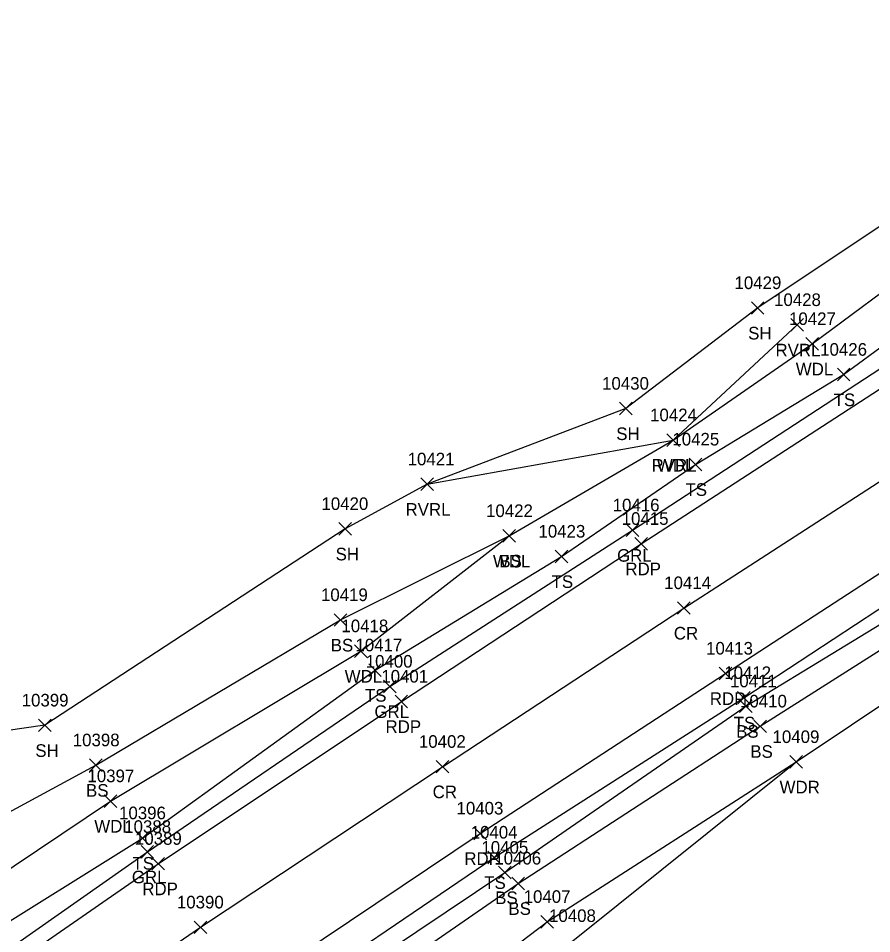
# Model space of a CAD drawing. Extents: x 1651685 to 1653558, y 889533 to 891085.
# Drawn here: x 1652971.5 to 1653107, y 890725 to 890870.3 of the extents above; entities that cross this region are included whole.
import ezdxf

# ---------------------------------------------------------------- set-up
doc = ezdxf.new("R2010")
doc.units = 0
for name, color, linetype in [('L_A', 7, 'Continuous'), ('L_I', 7, 'Continuous'), ('L_TIC', 7, 'Continuous'), ('LAWA', 7, 'Continuous'), ('LAWE', 7, 'Continuous'), ('LELB', 7, 'Continuous'), ('LSOGP', 7, 'Continuous'), ('P_A', 7, 'Continuous'), ('P_I', 7, 'Continuous'), ('P_TIC', 7, 'Continuous'), ('PET', 7, 'Continuous'), ('PRC', 7, 'Continuous'), ('R_A', 7, 'Continuous'), ('R_I', 7, 'Continuous'), ('R_TIC', 7, 'Continuous'), ('RGR', 7, 'Continuous')]:
    doc.layers.add(name, color=color, linetype=linetype)

msp = doc.modelspace()

# ---------------------------------------------------------------- linework, layer by layer
at = {"layer": 'L_TIC'}
for points in [[(1653087.88, 890823.36), (1653089.88, 890825.36)], [(1653089.88, 890823.36), (1653087.88, 890825.36)], [(1653094.15, 890820.67), (1653096.15, 890822.67)], [(1653096.15, 890820.67), (1653094.15, 890822.67)], [(1653096.52, 890817.66), (1653098.52, 890819.66)], [(1653098.52, 890817.66), (1653096.52, 890819.66)], [(1653101.53, 890812.78), (1653103.53, 890814.78)], [(1653103.53, 890812.78), (1653101.53, 890814.78)], [(1653066.94, 890807.39), (1653068.94, 890809.39)], [(1653068.94, 890807.39), (1653066.94, 890809.39)], [(1653074.47, 890802.38), (1653076.47, 890804.38)], [(1653076.47, 890802.38), (1653074.47, 890804.38)], [(1653074.47, 890802.38), (1653076.47, 890804.38)], [(1653076.47, 890802.38), (1653074.47, 890804.38)], [(1653078.01, 890798.53), (1653080.01, 890800.53)], [(1653080.01, 890798.53), (1653078.01, 890800.53)], [(1653035.42, 890795.38), (1653037.42, 890797.38)], [(1653037.42, 890795.38), (1653035.42, 890797.38)], [(1653022.39, 890788.29), (1653024.39, 890790.29)], [(1653024.39, 890788.29), (1653022.39, 890790.29)], [(1653048.43, 890787.17), (1653050.43, 890789.17)], [(1653050.43, 890787.17), (1653048.43, 890789.17)], [(1653048.43, 890787.17), (1653050.43, 890789.17)], [(1653050.43, 890787.17), (1653048.43, 890789.17)], [(1653056.75, 890783.91), (1653058.75, 890785.91)], [(1653058.75, 890783.91), (1653056.75, 890785.91)], [(1653021.66, 890773.83), (1653023.66, 890775.83)], [(1653023.66, 890773.83), (1653021.66, 890775.83)], [(1653024.9, 890768.89), (1653026.9, 890770.89)], [(1653026.9, 890768.89), (1653024.9, 890770.89)], [(1653027.13, 890765.86), (1653029.13, 890767.86)], [(1653029.13, 890765.86), (1653027.13, 890767.86)], [(1653085.67, 890761.46), (1653087.67, 890763.46)], [(1653087.67, 890761.46), (1653085.67, 890763.46)], [(1653086.02, 890760.14), (1653088.02, 890762.14)], [(1653088.02, 890760.14), (1653086.02, 890762.14)], [(1652974.72, 890757.1), (1652976.72, 890759.1)], [(1652976.72, 890757.1), (1652974.72, 890759.1)], [(1653088.27, 890756.95), (1653090.27, 890758.95)], [(1653090.27, 890756.95), (1653088.27, 890758.95)], [(1653094, 890751.3), (1653096, 890753.3)], [(1653096, 890751.3), (1653094, 890753.3)], [(1652982.82, 890750.78), (1652984.82, 890752.78)], [(1652984.82, 890750.78), (1652982.82, 890752.78)], [(1652985.15, 890745.08), (1652987.15, 890747.08)], [(1652987.15, 890745.08), (1652985.15, 890747.08)], [(1652990.22, 890739.2), (1652992.22, 890741.2)], [(1652992.22, 890739.2), (1652990.22, 890741.2)], [(1653046.06, 890736.13), (1653048.06, 890738.13)], [(1653048.06, 890736.13), (1653046.06, 890738.13)], [(1653047.76, 890733.73), (1653049.76, 890735.73)], [(1653049.76, 890733.73), (1653047.76, 890735.73)], [(1653049.87, 890732.01), (1653051.87, 890734.01)], [(1653051.87, 890732.01), (1653049.87, 890734.01)], [(1653054.48, 890725.92), (1653056.48, 890727.92)], [(1653056.48, 890725.92), (1653054.48, 890727.92)]]:
    msp.add_lwpolyline(points, dxfattribs=at)
at = {"layer": 'LAWA'}
for points in [[(1652817.98, 890613.54), (1652840.14, 890627.46), (1652861.15, 890647.29), (1652878.51, 890666.18), (1652884.26, 890671.52), (1652922.69, 890701.4), (1652959.19, 890728.02), (1652986.15, 890746.08), (1653025.9, 890769.89), (1653049.43, 890788.17), (1653075.47, 890803.38), (1653097.52, 890818.66), (1653132.33, 890844.48)], [(1652833.35, 890477.68), (1652833.39, 890492.3), (1652850.18, 890532.6), (1652867.73, 890564.2), (1652876.6, 890576.01), (1652892.95, 890598.85), (1652902.11, 890607.6), (1652908.8, 890618.44), (1652924.22, 890630.58), (1652962.12, 890654.07), (1652988.27, 890674.02), (1653019.66, 890699.72), (1653055.48, 890726.92), (1653095, 890752.3), (1653138.9, 890781.66), (1653162.63, 890798.14), (1653173.84, 890802.86)]]:
    msp.add_lwpolyline(points, dxfattribs=at)
at = {"layer": 'LAWE'}
msp.add_lwpolyline([(1653036.42, 890796.38), (1653075.47, 890803.38), (1653095.15, 890821.67)], dxfattribs=at)
at = {"layer": 'LELB'}
for points in [[(1652773.03, 890464.56), (1652787.9, 890509.35), (1652802.92, 890548.75), (1652814.17, 890571.87), (1652832.16, 890602.17), (1652848.73, 890624.66), (1652866.01, 890644.23), (1652889.12, 890668.57), (1652926.33, 890696.32), (1652964.24, 890723.35), (1652991.22, 890740.2), (1653028.13, 890766.86), (1653057.75, 890784.91), (1653079.01, 890799.53), (1653102.53, 890813.78), (1653139.28, 890840.79)], [(1652801.17, 890441.9), (1652819.95, 890497.78), (1652834.5, 890541.46), (1652846.59, 890562.12), (1652860.39, 890582.03), (1652876.07, 890602.68), (1652893.78, 890623.65), (1652912.56, 890642.08), (1652928.52, 890655.01), (1652947.04, 890668.65), (1652977.97, 890691.06), (1653009.95, 890711.96), (1653047.06, 890737.13), (1653086.67, 890762.46), (1653129.22, 890790.4), (1653161.56, 890810.77), (1653178.09, 890819.36), (1653180.64, 890814.31), (1653173.84, 890802.86)], [(1652803.19, 890441), (1652820.95, 890497.33), (1652835.58, 890541.15), (1652847.79, 890560.97), (1652861.63, 890580.86), (1652877.83, 890601.57), (1652890.21, 890617.22), (1652895.56, 890622.27), (1652897.12, 890622.95), (1652897.22, 890624.03), (1652915.57, 890639.3), (1652930.05, 890653.23), (1652948.11, 890667.03), (1652978.83, 890689.41), (1653011.67, 890709.88), (1653048.76, 890734.73), (1653087.02, 890761.14), (1653131.31, 890788.11), (1653159.98, 890805.73), (1653164.16, 890807.03), (1653164.17, 890807.66), (1653169.82, 890813.7), (1653178.09, 890819.36)], [(1652803.19, 890441), (1652822.35, 890480.19), (1652822.96, 890495.87), (1652838.19, 890539.83), (1652849.62, 890560.27), (1652863.19, 890579.04), (1652878.87, 890600.11), (1652891.82, 890615.8), (1652896.5, 890621.01), (1652897.47, 890622.7), (1652898.8, 890623.23), (1652915.57, 890639.3), (1652950.1, 890665.22), (1652980.52, 890686.66), (1653013.67, 890707.26), (1653050.87, 890733.01), (1653089.27, 890757.95), (1653133.42, 890785.98), (1653160.95, 890802.08), (1653164.63, 890804.85), (1653167.22, 890806.35), (1653170.81, 890811.17), (1653178.09, 890819.36)], [(1652740.63, 890407.57), (1652746.83, 890413.23), (1652755.32, 890445.88), (1652760.35, 890468.2), (1652780.77, 890512.23), (1652796.45, 890551.5), (1652807.59, 890577.74), (1652825.47, 890605.79), (1652840.14, 890627.46), (1652854.42, 890651.04), (1652870.71, 890668.15), (1652876.32, 890668.87), (1652880.71, 890674.05), (1652916.29, 890707.34), (1652954.78, 890736.09), (1652983.82, 890751.78), (1653022.66, 890774.83), (1653049.43, 890788.17)]]:
    msp.add_lwpolyline(points, dxfattribs=at)
at = {"layer": 'LSOGP'}
for points in [[(1653191.35, 890868.11), (1653139.25, 890847.21), (1653133.81, 890854.84), (1653132.26, 890853.62), (1653128.23, 890850.65), (1653088.88, 890824.36), (1653067.93, 890808.39), (1653036.42, 890796.38), (1653023.39, 890789.29), (1652975.72, 890758.11), (1652938.51, 890752.73), (1652900.6, 890736.09), (1652902.13, 890723.86), (1652868.79, 890705.34), (1652839.11, 890687.76), (1652822.21, 890657.08), (1652787.43, 890617.81), (1652783.5, 890592.65), (1652777.63, 890568.95), (1652768.73, 890549.07), (1652760.18, 890544.48), (1652755.23, 890514.52), (1652738.16, 890487.37)], [(1652860.84, 890470.43), (1652866.91, 890496.63), (1652876.03, 890531.03), (1652888.38, 890556.27), (1652912.99, 890585.04), (1652934.21, 890597.75), (1652965.72, 890622.73), (1652993.55, 890638.61), (1652995.94, 890655.58), (1652988.27, 890674.02), (1653019.66, 890699.72), (1653059.51, 890723.89), (1653095, 890752.3), (1653138.9, 890781.66), (1653162.63, 890798.14), (1653173.85, 890802.86), (1653182.19, 890805.28), (1653198.8, 890815.08)]]:
    msp.add_lwpolyline(points, dxfattribs=at)
at = {"layer": 'P_TIC'}
for points in [[(1653069.4, 890785.93), (1653071.4, 890787.93)], [(1653071.4, 890785.93), (1653069.4, 890787.93)], [(1653076.14, 890775.73), (1653078.14, 890777.73)], [(1653078.14, 890775.73), (1653076.14, 890777.73)], [(1653082.79, 890765.34), (1653084.79, 890767.34)], [(1653084.79, 890765.34), (1653082.79, 890767.34)], [(1653031.31, 890760.89), (1653033.31, 890762.89)], [(1653033.31, 890760.89), (1653031.31, 890762.89)], [(1653037.85, 890750.54), (1653039.85, 890752.54)], [(1653039.85, 890750.54), (1653037.85, 890752.54)], [(1653043.82, 890739.95), (1653045.82, 890741.95)], [(1653045.82, 890739.95), (1653043.82, 890741.95)], [(1652992.7, 890735.14), (1652994.7, 890737.14)], [(1652994.7, 890735.14), (1652992.7, 890737.14)], [(1652999.43, 890725.04), (1653001.43, 890727.04)], [(1653001.43, 890725.04), (1652999.43, 890727.04)]]:
    msp.add_lwpolyline(points, dxfattribs=at)
at = {"layer": 'PET'}
for points in [[(1652776.68, 890458.63), (1652791.9, 890507.53), (1652801.72, 890533.82), (1652810.09, 890553.36), (1652823.07, 890577.38), (1652836.65, 890598.71), (1652853.5, 890620.62), (1652874.5, 890644.55), (1652894.69, 890663.43), (1652909.83, 890677.02), (1652929.28, 890691.96), (1652967.44, 890717.98), (1652993.7, 890736.14), (1653032.31, 890761.89), (1653070.4, 890786.93), (1653112.15, 890813.99), (1653148.48, 890837.47), (1653192.87, 890865.71), (1653235.94, 890893.09), (1653280.18, 890921.16), (1653320.29, 890946.68)], [(1652797.7, 890444.76), (1652815.98, 890499.36), (1652826.44, 890526.94), (1652833.17, 890541.97), (1652844.38, 890563.93), (1652857.27, 890583.87), (1652872.84, 890604.95), (1652891.59, 890626.08), (1652910.84, 890643.86), (1652926.01, 890657.3), (1652944.49, 890672.05), (1652975.79, 890694.46), (1653007.52, 890715.91), (1653044.82, 890740.95), (1653083.79, 890766.34), (1653126.92, 890794.39), (1653162.42, 890817.19), (1653177.23, 890826.53), (1653212.82, 890849.27), (1653251.6, 890873.99), (1653294.22, 890900.69), (1653334.65, 890925.85)]]:
    msp.add_lwpolyline(points, dxfattribs=at)
at = {"layer": 'PRC'}
msp.add_lwpolyline([(1652786.21, 890448.94), (1652804.54, 890503.78), (1652815.08, 890532.72), (1652822.08, 890547.99), (1652834.04, 890571.05), (1652846.73, 890591.11), (1652862.72, 890612.73), (1652882.99, 890635.62), (1652902.76, 890654.37), (1652917.73, 890667.19), (1652936.47, 890681.71), (1652967.99, 890703.84), (1653000.43, 890726.04), (1653038.85, 890751.54), (1653077.14, 890776.73), (1653119.4, 890804.03), (1653156.21, 890827.39), (1653198.86, 890855.33), (1653243.54, 890883.44), (1653287.35, 890911.24), (1653327.74, 890936.2)], dxfattribs=at)
at = {"layer": 'R_TIC'}
for points in [[(1653068.01, 890788.08), (1653070.01, 890790.08)], [(1653070.01, 890788.08), (1653068.01, 890790.08)], [(1653029.5, 890763.27), (1653031.5, 890765.27)], [(1653031.5, 890763.27), (1653029.5, 890765.27)], [(1652990.99, 890737.03), (1652992.99, 890739.03)], [(1652992.99, 890737.03), (1652990.99, 890739.03)]]:
    msp.add_lwpolyline(points, dxfattribs=at)
at = {"layer": 'RGR'}
msp.add_lwpolyline([(1652753.62, 890407.5), (1652763.75, 890431.04), (1652774.48, 890459.79), (1652790.93, 890508.17), (1652800.51, 890534.29), (1652809.1, 890554.07), (1652821.88, 890578.18), (1652835.53, 890599.08), (1652852.44, 890621.25), (1652873.86, 890645.38), (1652894.3, 890664.88), (1652909.53, 890677.55), (1652928.71, 890692.69), (1652967.13, 890720.62), (1652991.99, 890738.03), (1653030.5, 890764.27), (1653069.01, 890789.08), (1653110.73, 890816.31), (1653147.12, 890839.54), (1653191.34, 890868.1), (1653234.07, 890895.44), (1653279.07, 890923.79), (1653318.83, 890948.74)], dxfattribs=at)

# ---------------------------------------------------------------- texts
at = {"layer": 'L_A'}
for s, p in [('SH', (1653087.37, 890819.36)), ('RVRL', (1653091.71, 890816.67)), ('WDL', (1653094.93, 890813.66)), ('TS', (1653100.94, 890808.78)), ('SH', (1653066.43, 890803.39)), ('RVRL', (1653072.04, 890798.38)), ('WDL', (1653072.89, 890798.38)), ('TS', (1653077.42, 890794.53)), ('RVRL', (1653032.98, 890791.38)), ('SH', (1653021.88, 890784.29)), ('WDL', (1653046.85, 890783.17)), ('BS', (1653047.87, 890783.17)), ('TS', (1653056.16, 890779.91)), ('BS', (1653021.1, 890769.83)), ('WDL', (1653023.32, 890764.89)), ('TS', (1653026.54, 890761.86)), ('TS', (1653085.08, 890757.46)), ('BS', (1653085.46, 890756.14)), ('SH', (1652974.21, 890753.1)), ('BS', (1653087.71, 890752.95)), ('BS', (1652982.26, 890746.78)), ('WDR', (1653092.36, 890747.3)), ('WDL', (1652983.57, 890741.08)), ('TS', (1652989.63, 890735.2)), ('TS', (1653045.47, 890732.13)), ('BS', (1653047.21, 890729.73)), ('BS', (1653049.31, 890728.01))]:
    msp.add_text(s, height=2, dxfattribs=at).set_placement(p)
at = {"layer": 'L_I'}
for s, p in [('10429', (1653085.2, 890827.36)), ('10428', (1653091.48, 890824.67)), ('10427', (1653093.85, 890821.66)), ('10426', (1653098.8, 890816.78)), ('10430', (1653064.18, 890811.39)), ('10424', (1653071.8, 890806.38)), ('10424', (1653071.8, 890806.38)), ('10425', (1653075.34, 890802.53)), ('10421', (1653033.31, 890799.38)), ('10420', (1653019.63, 890792.29)), ('10422', (1653045.76, 890791.17)), ('10422', (1653045.76, 890791.17)), ('10423', (1653054.08, 890787.91)), ('10419', (1653019.55, 890777.83)), ('10418', (1653022.8, 890772.89)), ('10417', (1653025.03, 890769.86)), ('10412', (1653083.57, 890765.46)), ('10411', (1653084.48, 890764.14)), ('10399', (1652972.04, 890761.1)), ('10410', (1653086.08, 890760.95)), ('10398', (1652980.15, 890754.78)), ('10409', (1653091.24, 890755.3)), ('10397', (1652982.48, 890749.08)), ('10396', (1652987.5, 890743.2)), ('10404', (1653043.32, 890740.13)), ('10405', (1653045.02, 890737.73)), ('10406', (1653047.07, 890736.01)), ('10407', (1653051.73, 890729.92)), ('10408', (1653055.76, 890726.89))]:
    msp.add_text(s, height=2, dxfattribs=at).set_placement(p)
at = {"layer": 'P_A'}
for s, p in [('RDP', (1653067.88, 890781.93)), ('CR', (1653075.57, 890771.73)), ('RDP', (1653081.28, 890761.34)), ('RDP', (1653029.8, 890756.89)), ('CR', (1653037.28, 890746.54)), ('RDP', (1653042.31, 890735.95)), ('RDP', (1652991.19, 890731.14))]:
    msp.add_text(s, height=2, dxfattribs=at).set_placement(p)
at = {"layer": 'P_I'}
for s, p in [('10415', (1653067.29, 890789.93)), ('10414', (1653074.04, 890779.73)), ('10413', (1653080.69, 890769.34)), ('10401', (1653029.13, 890764.89)), ('10402', (1653035.1, 890754.54)), ('10403', (1653041.07, 890743.95)), ('10389', (1652990.02, 890739.14)), ('10390', (1652996.68, 890729.04))]:
    msp.add_text(s, height=2, dxfattribs=at).set_placement(p)
at = {"layer": 'R_A'}
for p in [(1653066.56, 890784.08), (1653028.04, 890759.27), (1652989.53, 890733.03)]:
    msp.add_text('GRL', height=2, dxfattribs=at).set_placement(p)
at = {"layer": 'R_I'}
for s, p in [('10416', (1653065.86, 890792.08)), ('10400', (1653026.66, 890767.27)), ('10388', (1652988.32, 890741.03))]:
    msp.add_text(s, height=2, dxfattribs=at).set_placement(p)

doc.saveas('drawing.dxf')
